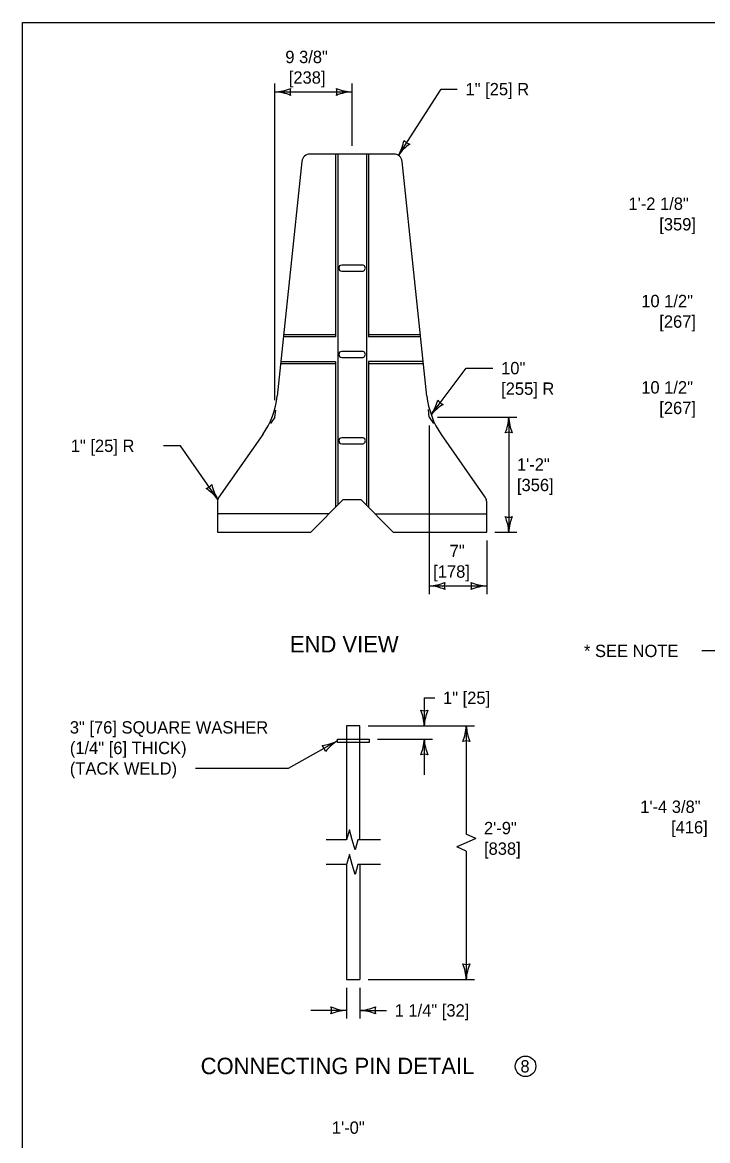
# Model space of a CAD drawing. Extents: x 49991.4 to 50021, y 49987.6 to 50011.4.
# Drawn here: x 49999.38 to 50002.72, y 49993.56 to 49999 of the extents above; entities that cross this region are included whole.
import ezdxf

# ---------------------------------------------------------------- set-up
doc = ezdxf.new("R2010")
doc.units = 0
for name, color, linetype in [('Level 1', 7, 'Continuous'), ('Level 2', 7, 'Continuous'), ('Level 3', 7, 'Continuous'), ('Level 4', 7, 'Continuous'), ('Level 6', 7, 'Continuous')]:
    doc.layers.add(name, color=color, linetype=linetype)

msp = doc.modelspace()

# ---------------------------------------------------------------- linework, layer by layer
at = {"layer": 'Level 1'}
for p, q in [((50001.1913, 49998.3586), (50000.7833, 49998.3586)), ((50000.9073, 49998.3586), (50000.9073, 49997.4688)), ((50000.9173, 49998.3586), (50000.9173, 49996.6507)), ((50001.0573, 49998.3586), (50001.0573, 49996.6507)), ((50001.0673, 49998.3586), (50001.0673, 49997.4688)), ((50000.7435, 49998.3228), (50000.6231, 49997.1814)), ((50001.3515, 49997.1814), (50001.2311, 49998.3228)), ((50001.0372, 49997.8184), (50000.9372, 49997.8184)), ((50000.9372, 49997.789), (50001.0372, 49997.789)), ((50000.9073, 49997.4688), (50000.6534, 49997.4688)), ((50000.9073, 49997.4788), (50000.6545, 49997.4788)), ((50001.3201, 49997.4788), (50001.0673, 49997.4788)), ((50001.3211, 49997.4688), (50001.0673, 49997.4688)), ((50000.6408, 49997.3488), (50000.9073, 49997.3488)), ((50000.9073, 49997.3488), (50000.9073, 49996.6405)), ((50001.0372, 49997.3984), (50000.9372, 49997.3984)), ((50000.9372, 49997.369), (50001.0372, 49997.369)), ((50001.3338, 49997.3488), (50001.0674, 49997.3488)), ((50001.0674, 49997.3488), (50001.0674, 49996.6404)), ((50000.9073, 49997.3388), (50000.6397, 49997.3388)), ((50001.3349, 49997.3387), (50001.0674, 49997.3387)), ((50000.553, 49996.994), (50000.3395, 49996.689)), ((50001.0373, 49996.9784), (50000.9373, 49996.9784)), ((50001.6351, 49996.689), (50001.4216, 49996.994)), ((50000.9373, 49996.949), (50001.0373, 49996.949)), ((50000.3323, 49996.666), (50000.3323, 49996.5186)), ((50000.9448, 49996.6786), (50000.7873, 49996.5186)), ((50000.9448, 49996.6786), (50001.0298, 49996.6786)), ((50001.0298, 49996.6786), (50001.1873, 49996.5186)), ((50001.6423, 49996.5186), (50001.6423, 49996.666)), ((50000.3323, 49996.5186), (50000.7873, 49996.5186)), ((50001.1873, 49996.5186), (50001.6423, 49996.5186)), ((50000.9607, 49995.5771), (50000.9607, 49995.023)), ((50001.0252, 49995.5771), (50000.9607, 49995.5771)), ((50001.0252, 49995.023), (50001.0252, 49995.5771)), ((50000.9157, 49995.5124), (50001.0705, 49995.5124)), ((50000.9157, 49995.496), (50000.9157, 49995.5124)), ((50001.0705, 49995.5124), (50001.0705, 49995.496)), ((50001.0705, 49995.496), (50000.9157, 49995.496)), ((50000.9607, 49994.9023), (50000.9607, 49994.3431)), ((50001.0252, 49994.9023), (50001.0252, 49994.3431)), ((50000.9607, 49994.3431), (50001.0252, 49994.3431))]:
    msp.add_line(p, q, dxfattribs=at)
msp.add_lwpolyline([(49999.3835, 49998.9992), (50016.7501, 49998.9992), (50016.7501, 49987.7988), (49999.3835, 49987.7988)], close=True, dxfattribs=at)
for centre, start, end in [((50000.9373, 49997.8037), 90.1418, 269.8582), ((50001.0375, 49997.8037), 268.9989, 91.0011), ((50000.9373, 49997.3837), 90.1418, 269.8582), ((50001.0375, 49997.3837), 268.9989, 91.0011), ((50000.9373, 49996.9637), 90.1418, 269.8582), ((50001.0376, 49996.9637), 268.9989, 91.0011)]:
    msp.add_arc(centre, 0.0147, start, end, dxfattribs=at)
for centre, major_axis, start_param, end_param in [((50000.7833, 49998.3186), (-0.04, 0), 4.712389, 6.178105), ((50001.1913, 49998.3186), (-0.04, 0), 3.246673, 4.712389), ((50000.2253, 49997.2234), (0.4, 0), 5.672459, 6.178105), ((50001.7492, 49997.2234), (-0.4, 0), 0.10508, 0.610726), ((50000.3723, 49996.666), (-0.04, 0), 5.672459, 6.283185), ((50001.6023, 49996.666), (0.04, 0), 0, 0.610726)]:
    msp.add_ellipse(centre, major_axis=major_axis, ratio=0.999982, start_param=start_param, end_param=end_param, dxfattribs=at)
at = {"layer": 'Level 2'}
msp.add_circle((50001.8313, 49993.9207), 0.05, dxfattribs=at)
at = {"layer": 'Level 3'}
for p, q in [((50000.6123, 49997.162), (50000.6123, 49998.701)), ((50000.6123, 49998.661), (50000.9873, 49998.661)), ((50000.9873, 49998.3986), (50000.9873, 49998.701)), ((50001.213, 49998.3522), (50001.4209, 49998.6743)), ((50001.4209, 49998.6743), (50001.4993, 49998.6743)), ((50001.3722, 49997.0899), (50001.5417, 49997.3173)), ((50001.5417, 49997.3173), (50001.6725, 49997.3173)), ((50000.6123, 49997.0786), (50000.5913, 49997.0486)), ((50000.6123, 49997.0786), (50000.616, 49997.1134)), ((50001.3623, 49997.0786), (50001.3584, 49997.1159)), ((50001.3623, 49997.0786), (50001.3839, 49997.0477)), ((50001.4023, 49997.0786), (50001.7895, 49997.0786)), ((50001.7495, 49997.0786), (50001.7495, 49996.5186)), ((50001.3623, 49997.0386), (50001.3623, 49996.2176)), ((50000.152, 49996.9394), (50000.0702, 49996.9394)), ((50000.3344, 49996.6789), (50000.152, 49996.9394)), ((50001.6423, 49996.4786), (50001.6423, 49996.2176)), ((50001.6823, 49996.5186), (50001.7895, 49996.5186)), ((50001.3623, 49996.2576), (50001.6423, 49996.2576)), ((50002.8033, 49995.9416), (50002.6888, 49995.9416)), ((50001.3387, 49995.7133), (50001.3897, 49995.7133)), ((50001.3387, 49995.7133), (50001.3387, 49995.5771)), ((50001.0652, 49995.5771), (50001.5831, 49995.5771)), ((50001.5431, 49995.5771), (50001.5431, 49995.0497)), ((50000.9157, 49995.5041), (50000.6765, 49995.3696)), ((50001.1105, 49995.5124), (50001.3787, 49995.5124)), ((50001.3387, 49995.5124), (50001.3387, 49995.339)), ((50000.6765, 49995.3696), (50000.2256, 49995.3696)), ((50001.5428, 49995.0085), (50001.4963, 49994.9879)), ((50001.5891, 49995.0292), (50001.5428, 49995.0085)), ((50001.5891, 49995.0292), (50001.5431, 49995.0497)), ((50001.5428, 49994.9673), (50001.4963, 49994.9879)), ((50001.5428, 49994.9673), (50001.5431, 49994.9672)), ((50001.5431, 49994.9672), (50001.5431, 49994.3431)), ((50000.9607, 49994.3031), (50000.9607, 49994.1529)), ((50001.0252, 49994.3031), (50001.0252, 49994.1529)), ((50001.0652, 49994.3431), (50001.5831, 49994.3431)), ((50000.9607, 49994.1929), (50000.7872, 49994.1929)), ((50001.0252, 49994.1929), (50001.1547, 49994.1929))]:
    msp.add_line(p, q, dxfattribs=at)
for centre, radius, start, end in [((50000.6008, 49998.8937), 0.233, 272.8273, 292.0772), ((50000.6031, 49998.4388), 0.2223, 67.456, 87.6395), ((50000.7405, 49998.661), 0.0548, 162.1388, 197.8612), ((50000.9964, 49998.8831), 0.2223, 247.456, 267.6395), ((50000.8591, 49998.661), 0.0548, 342.1388, 17.8612), ((50000.9988, 49998.4283), 0.233, 92.8273, 112.0772), ((50001.0112, 49998.4688), 0.233, 329.985, 349.2349), ((50001.3946, 49998.2241), 0.2223, 124.6137, 144.7972), ((50001.2825, 49998.4599), 0.0548, 219.2965, 255.0189), ((50001.1787, 49997.2198), 0.233, 326.126, 345.3759), ((50001.5448, 49996.9498), 0.2223, 120.7547, 140.9382), ((50001.4488, 49997.1927), 0.0548, 215.4376, 251.1599), ((50001.5274, 49997.0878), 0.2223, 337.456, 357.6395), ((50001.9823, 49997.0901), 0.233, 182.8273, 202.0772), ((50001.7495, 49996.9504), 0.0548, 72.1388, 107.8612), ((50000.2609, 49996.7839), 0.0548, 287.1308, 322.8531), ((50000.5216, 49996.7987), 0.2223, 192.448, 212.6315), ((50000.1503, 49996.536), 0.233, 37.8193, 57.0691), ((50001.7495, 49996.6469), 0.0548, 252.1388, 287.8612), ((50001.5168, 49996.5071), 0.233, 2.8273, 22.0772), ((50001.9717, 49996.5095), 0.2223, 157.456, 177.6395), ((50001.3508, 49996.4903), 0.233, 272.8273, 292.0772), ((50001.4905, 49996.2576), 0.0548, 162.1388, 197.8612), ((50001.6514, 49996.4798), 0.2223, 247.456, 267.6395), ((50001.5141, 49996.2576), 0.0548, 342.1388, 17.8612), ((50001.3531, 49996.0355), 0.2223, 67.456, 87.6395), ((50001.6538, 49996.0249), 0.233, 92.8273, 112.0772), ((50001.3387, 49995.7054), 0.0548, 252.1388, 287.8612), ((50001.106, 49995.5657), 0.233, 2.8273, 22.0772), ((50001.5608, 49995.568), 0.2223, 157.456, 177.6395), ((50001.3209, 49995.5863), 0.2223, 337.456, 357.6395), ((50001.7758, 49995.5886), 0.233, 182.8273, 202.0772), ((50000.8148, 49995.7023), 0.2223, 276.8047, 296.9882), ((50001.0398, 49995.3069), 0.233, 122.176, 141.4258), ((50001.1165, 49995.5216), 0.2223, 337.456, 357.6395), ((50001.5714, 49995.5239), 0.233, 182.8273, 202.0772), ((50001.5431, 49995.4489), 0.0548, 72.1388, 107.8612), ((50000.8039, 49995.4413), 0.0548, 11.4875, 47.2098), ((50001.3387, 49995.3842), 0.0548, 72.1388, 107.8612), ((50001.5431, 49994.4714), 0.0548, 252.1388, 287.8612), ((50001.3104, 49994.3317), 0.233, 2.8273, 22.0772), ((50001.7652, 49994.334), 0.2223, 157.456, 177.6395), ((50000.9698, 49994.415), 0.2223, 247.456, 267.6395), ((50000.8325, 49994.1929), 0.0548, 342.1388, 17.8612), ((50000.9722, 49993.9602), 0.233, 92.8273, 112.0772), ((50001.0137, 49994.4256), 0.233, 272.8273, 292.0772), ((50001.016, 49993.9708), 0.2223, 67.456, 87.6395), ((50001.1534, 49994.1929), 0.0548, 162.1388, 197.8612)]:
    msp.add_arc(centre, radius, start, end, dxfattribs=at)
at = {"layer": 'Level 4'}
for p, q in [((50000.8759, 49996.6086), (50000.3323, 49996.6086)), ((50001.0987, 49996.6086), (50001.6423, 49996.6086))]:
    msp.add_line(p, q, dxfattribs=at)
at = {"layer": 'Level 6'}
for p, q in [((50000.9744, 49995.0717), (50000.9607, 49995.023)), ((50000.9882, 49995.023), (50000.9744, 49995.0717)), ((50000.9607, 49995.023), (50000.8607, 49995.023)), ((50001.0019, 49994.9745), (50000.9882, 49995.023)), ((50001.0156, 49995.023), (50001.0019, 49994.9745)), ((50001.1252, 49995.023), (50001.0156, 49995.023)), ((50000.9607, 49994.9023), (50000.8607, 49994.9023)), ((50000.9744, 49994.9511), (50000.9607, 49994.9023)), ((50000.9882, 49994.9023), (50000.9744, 49994.9511)), ((50001.0019, 49994.8538), (50000.9882, 49994.9023)), ((50001.0156, 49994.9023), (50001.0019, 49994.8538)), ((50001.1252, 49994.9023), (50001.0156, 49994.9023))]:
    msp.add_line(p, q, dxfattribs=at)

# ---------------------------------------------------------------- texts
at = {"layer": 'Level 2'}
for s, height, p in [('9 3/8"', 0.06, (50000.6627, 49998.801)), ('[238]', 0.06, (50000.6796, 49998.701)), ('1" [25] R', 0.06, (50001.5393, 49998.6443)), ('1\'-2 1/8"', 0.06, (50002.3318, 49998.0871)), ('[359]', 0.06, (50002.4817, 49997.9871)), ('10 1/2"', 0.06, (50002.3941, 49997.6137)), ('[267]', 0.06, (50002.4817, 49997.5137)), ('10" ', 0.06, (50001.7125, 49997.2873)), ('[255] R', 0.06, (50001.7125, 49997.1873)), ('10 1/2"', 0.06, (50002.3941, 49997.1937)), ('[267]', 0.06, (50002.4817, 49997.0937)), ('1" [25] R', 0.06, (49999.6191, 49996.9094)), ('1\'-2" ', 0.06, (50001.7895, 49996.8187)), ('[356]', 0.06, (50001.7895, 49996.7187)), ('7"', 0.06, (50001.462, 49996.3976)), ('[178]', 0.06, (50001.3821, 49996.2976)), ('END VIEW', 0.08, (50000.6849, 49995.9341)), ('* SEE NOTE', 0.06, (50002.1155, 49995.9116)), ('1" [25]', 0.06, (50001.4297, 49995.6833)), ('3" [76] SQUARE WASHER', 0.06, (49999.6144, 49995.5396)), ('(1/4" [6] THICK)', 0.06, (49999.6144, 49995.4396)), ('(TACK WELD)', 0.06, (49999.6144, 49995.3396)), ('1\'-4 3/8"', 0.06, (50002.3891, 49995.1536)), ('[416]', 0.06, (50002.539, 49995.0536)), ('2\'-9"', 0.06, (50001.6291, 49995.0498)), ('[838]', 0.06, (50001.6291, 49994.9498)), ('1 1/4" [32]', 0.06, (50001.1947, 49994.1629)), ('CONNECTING PIN DETAIL', 0.08, (50000.2507, 49993.8826)), ('8', 0.06, (50001.8063, 49993.8907)), ('1\'-0"', 0.06, (50000.8889, 49993.5925))]:
    msp.add_text(s, height=height, dxfattribs=at).set_placement(p)

doc.saveas('drawing.dxf')
